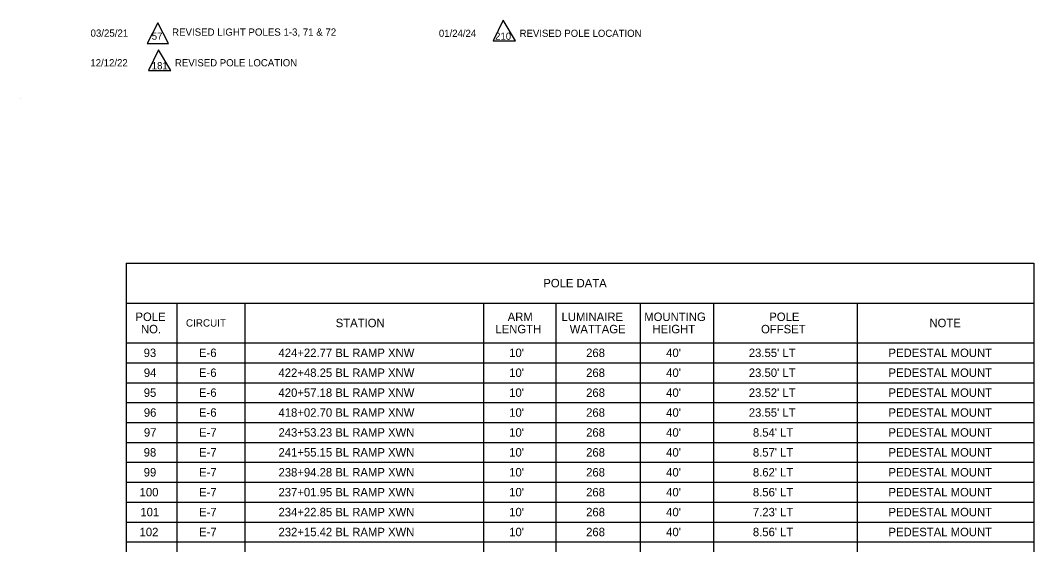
# Model space of a CAD drawing. Extents: x -818.1 to -802.4, y -2221.2 to -2187.7.
# Drawn here: x -818.09 to -809.69, y -2201.81 to -2197.46 of the extents above; entities that cross this region are included whole.
import ezdxf

# ---------------------------------------------------------------- set-up
doc = ezdxf.new("R2010")
doc.units = 0
for name, color, linetype in [('AdhocPoint_dp', 7, 'Continuous'), ('Cloud_dp', 7, 'Continuous'), ('SumBoxBorder_dp', 7, 'Continuous'), ('SumBoxLines_dp', 7, 'Continuous'), ('SumBoxLinesMin_dp', 7, 'Continuous'), ('TextLabel', 7, 'Continuous')]:
    doc.layers.add(name, color=color, linetype=linetype)

msp = doc.modelspace()

# ---------------------------------------------------------------- linework, layer by layer
at = {"layer": 'AdhocPoint_dp'}
msp.add_line((-818.0862, -2198.1071), (-818.0862, -2198.1071), dxfattribs=at)
at = {"layer": 'Cloud_dp'}
for points in [[(-816.946, -2197.4826), (-817.034, -2197.6522), (-816.8579, -2197.6522)], [(-814.0844, -2197.4606), (-814.1652, -2197.6318), (-813.9808, -2197.6318)], [(-816.9415, -2197.7044), (-817.0225, -2197.876), (-816.8377, -2197.876)]]:
    msp.add_lwpolyline(points, close=True, dxfattribs=at)
at = {"layer": 'SumBoxBorder_dp'}
for p, q in [((-817.2082, -2199.4742), (-809.6857, -2199.4742)), ((-817.2082, -2199.4742), (-817.2082, -2206.2692)), ((-809.6857, -2199.4742), (-809.6857, -2206.2692)), ((-817.2082, -2199.8042), (-809.6857, -2199.8042)), ((-817.2082, -2199.8042), (-809.6857, -2199.8042))]:
    msp.add_line(p, q, dxfattribs=at)
at = {"layer": 'SumBoxLines_dp'}
for p, q in [((-816.7882, -2199.8042), (-816.7882, -2206.2692)), ((-816.7882, -2199.8042), (-816.7882, -2206.2692)), ((-816.2257, -2199.8042), (-816.2257, -2206.2692)), ((-816.2257, -2199.8042), (-816.2257, -2206.2692)), ((-814.2457, -2199.8042), (-814.2457, -2206.2692)), ((-814.2457, -2199.8042), (-814.2457, -2206.2692)), ((-813.6457, -2199.8042), (-813.6457, -2206.2692)), ((-813.6457, -2199.8042), (-813.6457, -2206.2692)), ((-812.9482, -2199.8042), (-812.9482, -2206.2692)), ((-812.9482, -2199.8042), (-812.9482, -2206.2692)), ((-812.3407, -2199.8042), (-812.3407, -2206.2692)), ((-812.3407, -2199.8042), (-812.3407, -2206.2692)), ((-811.1482, -2199.8042), (-811.1482, -2206.2692)), ((-811.1482, -2199.8042), (-811.1482, -2206.2692)), ((-817.2082, -2200.1342), (-809.6857, -2200.1342))]:
    msp.add_line(p, q, dxfattribs=at)
at = {"layer": 'SumBoxLinesMin_dp'}
for p, q in [((-817.2082, -2200.1342), (-809.6857, -2200.1342)), ((-817.2082, -2200.2992), (-809.6857, -2200.2992)), ((-817.2082, -2200.2992), (-809.6857, -2200.2992)), ((-817.2082, -2200.4642), (-809.6857, -2200.4642)), ((-817.2082, -2200.4642), (-809.6857, -2200.4642)), ((-817.2082, -2200.6292), (-809.6857, -2200.6292)), ((-817.2082, -2200.6292), (-809.6857, -2200.6292)), ((-817.2082, -2200.7942), (-809.6857, -2200.7942)), ((-817.2082, -2200.7942), (-809.6857, -2200.7942)), ((-817.2082, -2200.9592), (-809.6857, -2200.9592)), ((-817.2082, -2200.9592), (-809.6857, -2200.9592)), ((-817.2082, -2201.1242), (-809.6857, -2201.1242)), ((-817.2082, -2201.1242), (-809.6857, -2201.1242)), ((-817.2082, -2201.2892), (-809.6857, -2201.2892)), ((-817.2082, -2201.2892), (-809.6857, -2201.2892)), ((-817.2082, -2201.4542), (-809.6857, -2201.4542)), ((-817.2082, -2201.4542), (-809.6857, -2201.4542)), ((-817.2082, -2201.6192), (-809.6857, -2201.6192)), ((-817.2082, -2201.6192), (-809.6857, -2201.6192)), ((-817.2082, -2201.7842), (-809.6857, -2201.7842)), ((-817.2082, -2201.7842), (-809.6857, -2201.7842))]:
    msp.add_line(p, q, dxfattribs=at)

# ---------------------------------------------------------------- texts
at = {"layer": 'Cloud_dp'}
for s, height, p in [('03/25/21', 0.06, (-817.5037, -2197.597)), ('57', 0.06, (-816.9966, -2197.622)), ('REVISED LIGHT POLES 1-3, 71 & 72', 0.06, (-816.8278, -2197.5884)), ('01/24/24', 0.05938, (-814.6162, -2197.5983)), ('210', 0.05938, (-814.1502, -2197.6226)), ('REVISED POLE LOCATION', 0.059382, (-813.9472, -2197.5983)), ('12/12/22', 0.05952, (-817.505, -2197.8424)), ('181', 0.05952, (-816.9966, -2197.8669)), ('REVISED POLE LOCATION', 0.05952, (-816.804, -2197.8424))]:
    msp.add_text(s, height=height, dxfattribs=at).set_placement(p)
at = {"layer": 'TextLabel'}
for s, height, p in [('POLE DATA', 0.07, (-813.7508, -2199.6742)), ('POLE', 0.07, (-817.1315, -2199.9532)), ('ARM', 0.07, (-814.0462, -2199.9532)), ('LUMINAIRE', 0.07, (-813.5996, -2199.9532)), ('MOUNTING', 0.07, (-812.9141, -2199.9532)), ('POLE', 0.07, (-811.8777, -2199.9532)), ('NO.', 0.07, (-817.0858, -2200.0552)), ('CIRCUIT', 0.06125, (-816.7129, -2199.9998)), ('STATION', 0.07, (-815.4715, -2200.0042)), ('LENGTH', 0.07, (-814.1476, -2200.0552)), ('WATTAGE', 0.07, (-813.5318, -2200.0552)), ('HEIGHT', 0.07, (-812.8459, -2200.0552)), ('OFFSET', 0.07, (-811.9459, -2200.0552)), ('NOTE', 0.07, (-810.5502, -2200.0042)), ('93', 0.07, (-817.0635, -2200.2517)), ('E-6', 0.07, (-816.6047, -2200.2517)), ('424+22.77 BL RAMP XNW', 0.07, (-815.9458, -2200.2517)), ("10'", 0.07, (-814.0336, -2200.2517)), ('268', 0.07, (-813.3958, -2200.2517)), ("40'", 0.07, (-812.7324, -2200.2517)), ("23.55' LT", 0.07, (-812.0475, -2200.2517)), ('PEDESTAL MOUNT', 0.07, (-810.8894, -2200.2517)), ('94', 0.07, (-817.0621, -2200.4167)), ('E-6', 0.07, (-816.6047, -2200.4167)), ('422+48.25 BL RAMP XNW', 0.07, (-815.9458, -2200.4167)), ("10'", 0.07, (-814.0336, -2200.4167)), ('268', 0.07, (-813.3958, -2200.4167)), ("40'", 0.07, (-812.7324, -2200.4167)), ("23.50' LT", 0.07, (-812.0475, -2200.4167)), ('PEDESTAL MOUNT', 0.07, (-810.8894, -2200.4167)), ('95', 0.07, (-817.0626, -2200.5817)), ('E-6', 0.07, (-816.6047, -2200.5817)), ('420+57.18 BL RAMP XNW', 0.07, (-815.9458, -2200.5817)), ("10'", 0.07, (-814.0336, -2200.5817)), ('268', 0.07, (-813.3958, -2200.5817)), ("40'", 0.07, (-812.7324, -2200.5817)), ("23.52' LT", 0.07, (-812.0475, -2200.5817)), ('PEDESTAL MOUNT', 0.07, (-810.8894, -2200.5817)), ('96', 0.07, (-817.0621, -2200.7467)), ('E-6', 0.07, (-816.6047, -2200.7467)), ('418+02.70 BL RAMP XNW', 0.07, (-815.9458, -2200.7467)), ("10'", 0.07, (-814.0336, -2200.7467)), ('268', 0.07, (-813.3958, -2200.7467)), ("40'", 0.07, (-812.7324, -2200.7467)), ("23.55' LT", 0.07, (-812.0475, -2200.7467)), ('PEDESTAL MOUNT', 0.07, (-810.8894, -2200.7467)), ('97', 0.07, (-817.0615, -2200.9117)), ('E-7', 0.07, (-816.6041, -2200.9117)), ('243+53.23 BL RAMP XWN', 0.07, (-815.9458, -2200.9117)), ("10'", 0.07, (-814.0336, -2200.9117)), ('268', 0.07, (-813.3958, -2200.9117)), ("40'", 0.07, (-812.7324, -2200.9117)), ("8.54' LT", 0.07, (-812.0137, -2200.9117)), ('PEDESTAL MOUNT', 0.07, (-810.8894, -2200.9117)), ('98', 0.07, (-817.0632, -2201.0767)), ('E-7', 0.07, (-816.6041, -2201.0767)), ('241+55.15 BL RAMP XWN', 0.07, (-815.9458, -2201.0767)), ("10'", 0.07, (-814.0336, -2201.0767)), ('268', 0.07, (-813.3958, -2201.0767)), ("40'", 0.07, (-812.7324, -2201.0767)), ("8.57' LT", 0.07, (-812.0137, -2201.0767)), ('PEDESTAL MOUNT', 0.07, (-810.8894, -2201.0767)), ('99', 0.07, (-817.0631, -2201.2417)), ('E-7', 0.07, (-816.6041, -2201.2417)), ('238+94.28 BL RAMP XWN', 0.07, (-815.9458, -2201.2417)), ("10'", 0.07, (-814.0336, -2201.2417)), ('268', 0.07, (-813.3958, -2201.2417)), ("40'", 0.07, (-812.7324, -2201.2417)), ("8.62' LT", 0.07, (-812.0137, -2201.2417)), ('PEDESTAL MOUNT', 0.07, (-810.8894, -2201.2417)), ('100', 0.07, (-817.0968, -2201.4067)), ('E-7', 0.07, (-816.6041, -2201.4067)), ('237+01.95 BL RAMP XWN', 0.07, (-815.9458, -2201.4067)), ("10'", 0.07, (-814.0336, -2201.4067)), ('268', 0.07, (-813.3958, -2201.4067)), ("40'", 0.07, (-812.7324, -2201.4067)), ("8.56' LT", 0.07, (-812.0137, -2201.4067)), ('PEDESTAL MOUNT', 0.07, (-810.8894, -2201.4067)), ('101', 0.07, (-817.0906, -2201.5717)), ('E-7', 0.07, (-816.6041, -2201.5717)), ('234+22.85 BL RAMP XWN', 0.07, (-815.9458, -2201.5717)), ("10'", 0.07, (-814.0336, -2201.5717)), ('268', 0.07, (-813.3958, -2201.5717)), ("40'", 0.07, (-812.7324, -2201.5717)), ("7.23' LT", 0.07, (-812.0137, -2201.5717)), ('PEDESTAL MOUNT', 0.07, (-810.8894, -2201.5717)), ('102', 0.07, (-817.0973, -2201.7367)), ('E-7', 0.07, (-816.6041, -2201.7367)), ('232+15.42 BL RAMP XWN', 0.07, (-815.9458, -2201.7367)), ("10'", 0.07, (-814.0336, -2201.7367)), ('268', 0.07, (-813.3958, -2201.7367)), ("40'", 0.07, (-812.7324, -2201.7367)), ("8.56' LT", 0.07, (-812.0137, -2201.7367)), ('PEDESTAL MOUNT', 0.07, (-810.8894, -2201.7367))]:
    msp.add_text(s, height=height, dxfattribs=at).set_placement(p)

doc.saveas('drawing.dxf')
